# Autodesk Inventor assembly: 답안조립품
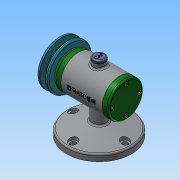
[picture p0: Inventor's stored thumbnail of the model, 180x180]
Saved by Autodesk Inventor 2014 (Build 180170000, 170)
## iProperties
Created: 2018-12
Part Number: 답안조립품
Document SubType Name: Assembly
Designer: net
Author: net
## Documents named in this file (15)
- C:\Users\net\Desktop\481207V1044\답안조립품.iam
- C:\Users\net\Desktop\481207V1044\본체.ipt
- C:\Users\net\Desktop\481207V1044\축.ipt
- C:\Users\net\Desktop\481207V1044\베어링 15 x 32 x 9.ipt
- C:\Users\net\Desktop\481207V1044\키 3 x 3 x 12.ipt
- C:\Users\net\Desktop\481207V1044\뒤커버.ipt
- C:\Users\net\Desktop\481207V1044\볼트 M4 x 12.ipt
- C:\Users\net\Desktop\481207V1044\앞커버.ipt
- C:\Users\net\Desktop\481207V1044\오일 실 15 25 7.ipt
- C:\Users\net\Desktop\481207V1044\V벨트풀리.ipt
- C:\Users\net\Desktop\481207V1044\와셔 8x17.ipt
- C:\Users\net\Desktop\481207V1044\스프링와셔 8.ipt
- C:\Users\net\Desktop\481207V1044\너트 M8.ipt
- 너트 M8.ipt
- C:\Users\net\Desktop\481207V1044\고무캡.ipt
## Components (2 placed, 2 different names)
1. V벨트풀리:1
2. 고무캡:1
